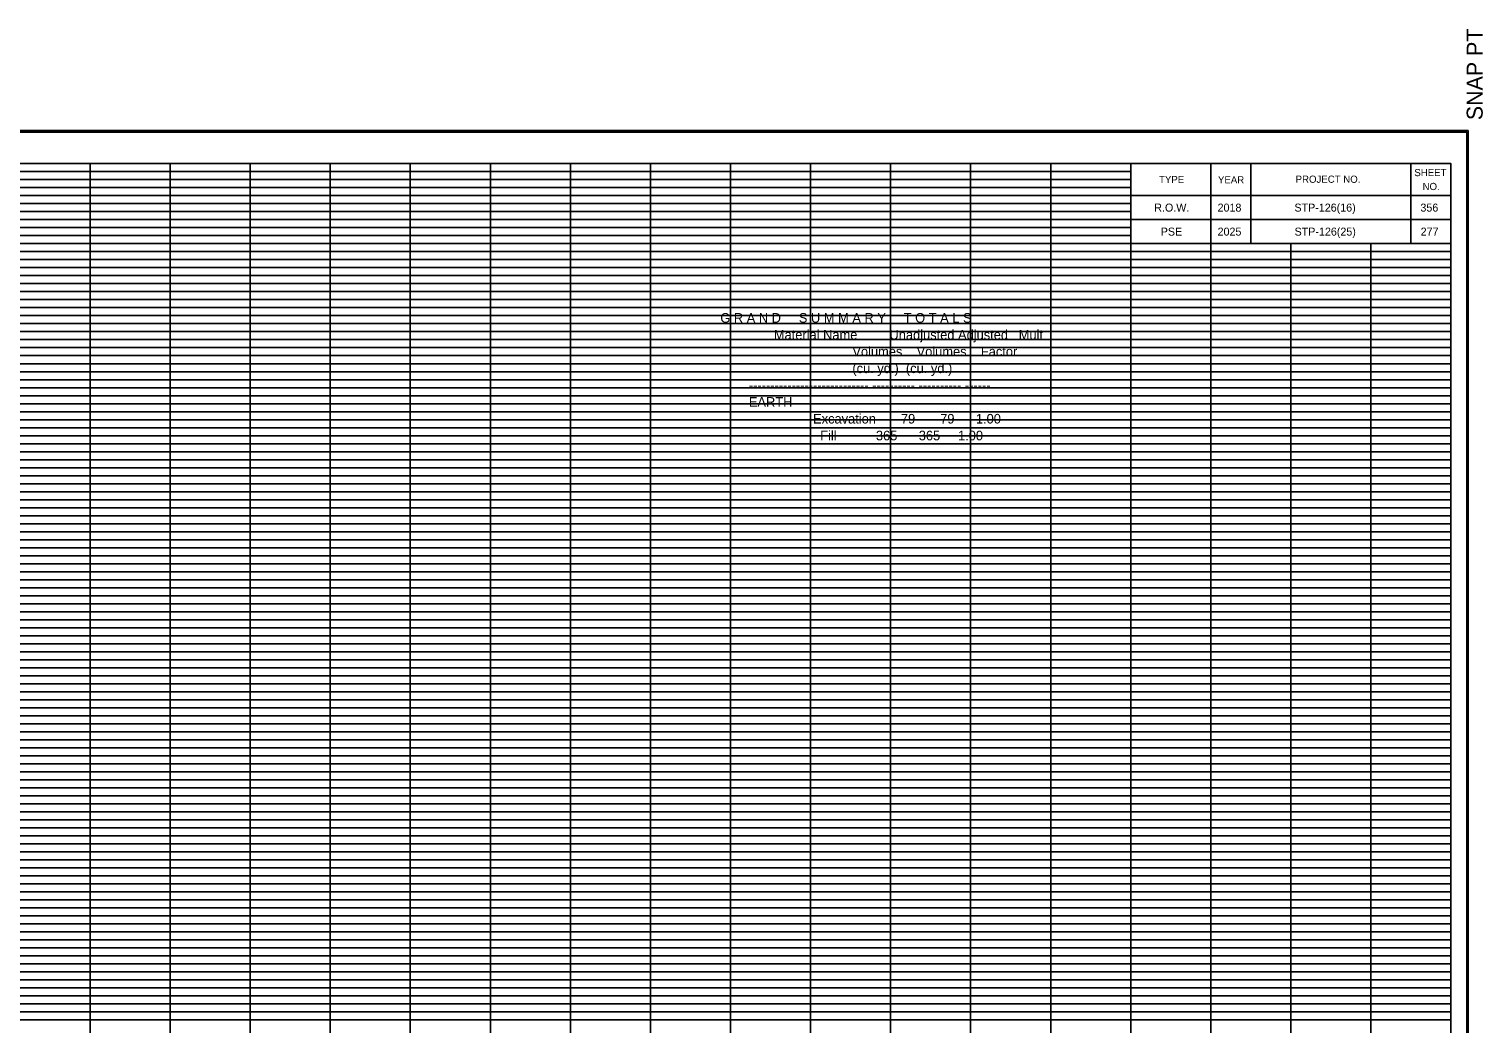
# Model space of a CAD drawing. Extents: x 980 to 1324, y 978 to 1497.
# Drawn here: x 1142.4 to 1324, y 1372.5 to 1496.8 of the extents above; entities that cross this region are included whole.
import ezdxf

# ---------------------------------------------------------------- set-up
doc = ezdxf.new("R2010")
doc.units = 0
for name, color, linetype in [('DESIGN - SCRATCH - User 1', 7, 'Continuous'), ('DESIGN - SHEET - Corner Text', 7, 'Continuous'), ('DESIGN - SHEET - Light Grid', 7, 'Continuous'), ('DESIGN - SHEET - Linework', 7, 'Continuous'), ('DESIGN - SHEET - Plot Shape', 7, 'Continuous'), ('DESIGN - TYPICAL - Finished Grade and Subgrade', 7, 'Continuous'), ('DESIGN - TYPICAL - Text', 7, 'Continuous')]:
    doc.layers.add(name, color=color, linetype=linetype)

# ---------------------------------------------------------------- blocks, each defined once
blk = doc.blocks.new('XSTSHT')
at = {"layer": 'DESIGN - SCRATCH - User 1'}
for p, q in [((28.5, 20.45), (28.5, 20.45)), ((29.24, 20.45), (29.24, 20.45)), ((30.49, 20.45), (30.49, 20.45)), ((31.74, 20.45), (31.74, 20.45)), ((28.5, 20.15), (28.5, 20.15)), ((29.24, 20.15), (29.24, 20.15)), ((30.49, 20.15), (30.49, 20.15)), ((31.74, 20.15), (31.74, 20.15))]:
    blk.add_line(p, q, dxfattribs=at)
at = {"layer": 'DESIGN - SHEET - Light Grid'}
for p, q in [((8, 20.9), (16, 20.9)), ((16, 20.9), (24, 20.9)), ((24, 20.9), (28, 20.9)), ((8, 20.8), (16, 20.8)), ((16, 20.8), (24, 20.8)), ((24, 20.8), (28, 20.8)), ((8, 20.7), (16, 20.7)), ((8, 20.6), (16, 20.6)), ((16, 20.7), (24, 20.7)), ((16, 20.6), (24, 20.6)), ((24, 20.7), (28, 20.7)), ((24, 20.6), (28, 20.6)), ((8, 20.5), (16, 20.5)), ((8, 20.4), (16, 20.4)), ((16, 20.5), (24, 20.5)), ((16, 20.4), (24, 20.4)), ((24, 20.5), (28, 20.5)), ((24, 20.4), (28, 20.4)), ((8, 20.3), (16, 20.3)), ((8, 20.2), (16, 20.2)), ((16, 20.3), (24, 20.3)), ((16, 20.2), (24, 20.2)), ((24, 20.3), (28, 20.3)), ((24, 20.2), (28, 20.2)), ((8, 20.1), (16, 20.1)), ((16, 20.1), (24, 20.1)), ((24, 20.1), (28, 20.1)), ((8, 19.9), (16, 19.9)), ((8, 19.8), (16, 19.8)), ((16, 19.9), (24, 19.9)), ((16, 19.8), (24, 19.8)), ((24, 19.9), (32, 19.9)), ((24, 19.8), (32, 19.8)), ((8, 19.7), (16, 19.7)), ((16, 19.7), (24, 19.7)), ((24, 19.7), (32, 19.7)), ((8, 19.6), (16, 19.6)), ((8, 19.5), (16, 19.5)), ((16, 19.6), (24, 19.6)), ((16, 19.5), (24, 19.5)), ((24, 19.6), (32, 19.6)), ((24, 19.5), (32, 19.5)), ((8, 19.4), (16, 19.4)), ((8, 19.3), (16, 19.3)), ((16, 19.4), (24, 19.4)), ((16, 19.3), (24, 19.3)), ((24, 19.4), (32, 19.4)), ((24, 19.3), (32, 19.3)), ((8, 19.2), (16, 19.2)), ((8, 19.1), (16, 19.1)), ((16, 19.2), (24, 19.2)), ((16, 19.1), (24, 19.1)), ((24, 19.2), (32, 19.2)), ((24, 19.1), (32, 19.1)), ((8, 18.9), (16, 18.9)), ((16, 18.9), (24, 18.9)), ((24, 18.9), (32, 18.9)), ((8, 18.8), (16, 18.8)), ((16, 18.8), (24, 18.8)), ((24, 18.8), (32, 18.8)), ((8, 18.7), (16, 18.7)), ((8, 18.6), (16, 18.6)), ((16, 18.7), (24, 18.7)), ((16, 18.6), (24, 18.6)), ((24, 18.7), (32, 18.7)), ((24, 18.6), (32, 18.6)), ((8, 18.5), (16, 18.5)), ((8, 18.4), (16, 18.4)), ((16, 18.5), (24, 18.5)), ((16, 18.4), (24, 18.4)), ((24, 18.5), (32, 18.5)), ((24, 18.4), (32, 18.4)), ((8, 18.3), (16, 18.3)), ((8, 18.2), (16, 18.2)), ((16, 18.3), (24, 18.3)), ((16, 18.2), (24, 18.2)), ((24, 18.3), (32, 18.3)), ((24, 18.2), (32, 18.2)), ((8, 18.1), (16, 18.1)), ((16, 18.1), (24, 18.1)), ((24, 18.1), (32, 18.1)), ((8, 17.9), (16, 17.9)), ((8, 17.8), (16, 17.8)), ((16, 17.9), (24, 17.9)), ((16, 17.8), (24, 17.8)), ((24, 17.9), (32, 17.9)), ((24, 17.8), (32, 17.8)), ((8, 17.7), (16, 17.7)), ((16, 17.7), (24, 17.7)), ((24, 17.7), (32, 17.7)), ((8, 17.6), (16, 17.6)), ((8, 17.5), (16, 17.5)), ((16, 17.6), (24, 17.6)), ((16, 17.5), (24, 17.5)), ((24, 17.6), (32, 17.6)), ((24, 17.5), (32, 17.5)), ((8, 17.4), (16, 17.4)), ((8, 17.3), (16, 17.3)), ((16, 17.4), (24, 17.4)), ((16, 17.3), (24, 17.3)), ((24, 17.4), (32, 17.4)), ((24, 17.3), (32, 17.3)), ((8, 17.2), (16, 17.2)), ((8, 17.1), (16, 17.1)), ((16, 17.2), (24, 17.2)), ((16, 17.1), (24, 17.1)), ((24, 17.2), (32, 17.2)), ((24, 17.1), (32, 17.1)), ((8, 16.9), (16, 16.9)), ((16, 16.9), (24, 16.9)), ((24, 16.9), (32, 16.9)), ((8, 16.8), (16, 16.8)), ((16, 16.8), (24, 16.8)), ((24, 16.8), (32, 16.8)), ((8, 16.7), (16, 16.7)), ((8, 16.6), (16, 16.6)), ((16, 16.7), (24, 16.7)), ((16, 16.6), (24, 16.6)), ((24, 16.7), (32, 16.7)), ((24, 16.6), (32, 16.6)), ((8, 16.5), (16, 16.5)), ((8, 16.4), (16, 16.4)), ((16, 16.5), (24, 16.5)), ((16, 16.4), (24, 16.4)), ((24, 16.5), (32, 16.5)), ((24, 16.4), (32, 16.4)), ((8, 16.3), (16, 16.3)), ((8, 16.2), (16, 16.2)), ((16, 16.3), (24, 16.3)), ((16, 16.2), (24, 16.2)), ((24, 16.3), (32, 16.3)), ((24, 16.2), (32, 16.2)), ((8, 16.1), (16, 16.1)), ((16, 16.1), (24, 16.1)), ((24, 16.1), (32, 16.1)), ((8, 15.9), (16, 15.9)), ((16, 15.9), (24, 15.9)), ((24, 15.9), (32, 15.9)), ((8, 15.8), (16, 15.8)), ((8, 15.7), (16, 15.7)), ((16, 15.8), (24, 15.8)), ((16, 15.7), (24, 15.7)), ((24, 15.8), (32, 15.8)), ((24, 15.7), (32, 15.7)), ((8, 15.6), (16, 15.6)), ((8, 15.5), (16, 15.5)), ((16, 15.6), (24, 15.6)), ((16, 15.5), (24, 15.5)), ((24, 15.6), (32, 15.6)), ((24, 15.5), (32, 15.5)), ((8, 15.4), (16, 15.4)), ((8, 15.3), (16, 15.3)), ((16, 15.4), (24, 15.4)), ((16, 15.3), (24, 15.3)), ((24, 15.4), (32, 15.4)), ((24, 15.3), (32, 15.3)), ((8, 15.2), (16, 15.2)), ((8, 15.1), (16, 15.1)), ((16, 15.2), (24, 15.2)), ((16, 15.1), (24, 15.1)), ((24, 15.2), (32, 15.2)), ((24, 15.1), (32, 15.1)), ((8, 14.9), (16, 14.9)), ((16, 14.9), (24, 14.9)), ((24, 14.9), (32, 14.9)), ((8, 14.8), (16, 14.8)), ((16, 14.8), (24, 14.8)), ((24, 14.8), (32, 14.8)), ((8, 14.7), (16, 14.7)), ((8, 14.6), (16, 14.6)), ((16, 14.7), (24, 14.7)), ((16, 14.6), (24, 14.6)), ((24, 14.7), (32, 14.7)), ((24, 14.6), (32, 14.6)), ((8, 14.5), (16, 14.5)), ((8, 14.4), (16, 14.4)), ((16, 14.5), (24, 14.5)), ((16, 14.4), (24, 14.4)), ((24, 14.5), (32, 14.5)), ((24, 14.4), (32, 14.4)), ((8, 14.3), (16, 14.3)), ((8, 14.2), (16, 14.2)), ((16, 14.3), (24, 14.3)), ((16, 14.2), (24, 14.2)), ((24, 14.3), (32, 14.3)), ((24, 14.2), (32, 14.2)), ((8, 14.1), (16, 14.1)), ((16, 14.1), (24, 14.1)), ((24, 14.1), (32, 14.1)), ((8, 13.9), (16, 13.9)), ((16, 13.9), (24, 13.9)), ((24, 13.9), (32, 13.9)), ((8, 13.8), (16, 13.8)), ((8, 13.7), (16, 13.7)), ((16, 13.8), (24, 13.8)), ((16, 13.7), (24, 13.7)), ((24, 13.8), (32, 13.8)), ((24, 13.7), (32, 13.7)), ((8, 13.6), (16, 13.6)), ((8, 13.5), (16, 13.5)), ((16, 13.6), (24, 13.6)), ((16, 13.5), (24, 13.5)), ((24, 13.6), (32, 13.6)), ((24, 13.5), (32, 13.5)), ((8, 13.4), (16, 13.4)), ((8, 13.3), (16, 13.3)), ((16, 13.4), (24, 13.4)), ((16, 13.3), (24, 13.3)), ((24, 13.4), (32, 13.4)), ((24, 13.3), (32, 13.3)), ((8, 13.2), (16, 13.2)), ((8, 13.1), (16, 13.1)), ((16, 13.2), (24, 13.2)), ((16, 13.1), (24, 13.1)), ((24, 13.2), (32, 13.2)), ((24, 13.1), (32, 13.1)), ((8, 12.9), (16, 12.9)), ((16, 12.9), (24, 12.9)), ((24, 12.9), (32, 12.9)), ((8, 12.8), (16, 12.8)), ((16, 12.8), (24, 12.8)), ((24, 12.8), (32, 12.8)), ((8, 12.7), (16, 12.7)), ((8, 12.6), (16, 12.6)), ((16, 12.7), (24, 12.7)), ((16, 12.6), (24, 12.6)), ((24, 12.7), (32, 12.7)), ((24, 12.6), (32, 12.6)), ((8, 12.5), (16, 12.5)), ((8, 12.4), (16, 12.4)), ((16, 12.5), (24, 12.5)), ((16, 12.4), (24, 12.4)), ((24, 12.5), (32, 12.5)), ((24, 12.4), (32, 12.4)), ((8, 12.3), (16, 12.3)), ((8, 12.2), (16, 12.2)), ((16, 12.3), (24, 12.3)), ((16, 12.2), (24, 12.2)), ((24, 12.3), (32, 12.3)), ((24, 12.2), (32, 12.2)), ((8, 12.1), (16, 12.1)), ((16, 12.1), (24, 12.1)), ((24, 12.1), (32, 12.1)), ((8, 11.9), (16, 11.9)), ((16, 11.9), (24, 11.9)), ((24, 11.9), (32, 11.9)), ((8, 11.8), (16, 11.8)), ((8, 11.7), (16, 11.7)), ((16, 11.8), (24, 11.8)), ((16, 11.7), (24, 11.7)), ((24, 11.8), (32, 11.8)), ((24, 11.7), (32, 11.7)), ((8, 11.6), (16, 11.6)), ((8, 11.5), (16, 11.5)), ((16, 11.6), (24, 11.6)), ((16, 11.5), (24, 11.5)), ((24, 11.6), (32, 11.6)), ((24, 11.5), (32, 11.5)), ((8, 11.4), (16, 11.4)), ((8, 11.3), (16, 11.3)), ((16, 11.4), (24, 11.4)), ((16, 11.3), (24, 11.3)), ((24, 11.4), (32, 11.4)), ((24, 11.3), (32, 11.3)), ((8, 11.2), (16, 11.2)), ((8, 11.1), (16, 11.1)), ((16, 11.2), (24, 11.2)), ((16, 11.1), (24, 11.1)), ((24, 11.2), (32, 11.2)), ((24, 11.1), (32, 11.1)), ((8, 10.9), (16, 10.9)), ((16, 10.9), (24, 10.9)), ((24, 10.9), (32, 10.9)), ((8, 10.8), (16, 10.8)), ((16, 10.8), (24, 10.8)), ((24, 10.8), (32, 10.8)), ((8, 10.7), (16, 10.7)), ((8, 10.6), (16, 10.6)), ((16, 10.7), (24, 10.7)), ((16, 10.6), (24, 10.6)), ((24, 10.7), (32, 10.7)), ((24, 10.6), (32, 10.6)), ((8, 10.5), (16, 10.5)), ((8, 10.4), (16, 10.4)), ((16, 10.5), (24, 10.5)), ((16, 10.4), (24, 10.4)), ((24, 10.5), (32, 10.5)), ((24, 10.4), (32, 10.4)), ((8, 10.3), (16, 10.3)), ((16, 10.3), (24, 10.3)), ((24, 10.3), (32, 10.3))]:
    blk.add_line(p, q, dxfattribs=at)
at = {"layer": 'DESIGN - SHEET - Linework'}
for p, q in [((-1.823, 21.414), (32.217, 21.414)), ((32.217, 21.414), (32.217, -0.414)), ((15, 0), (15, 21)), ((16, 0), (16, 21)), ((17, 0), (17, 21)), ((18, 0), (18, 21)), ((19, 0), (19, 21)), ((20, 0), (20, 21)), ((21, 0), (21, 21)), ((22, 0), (22, 21)), ((23, 0), (23, 21)), ((24, 0), (24, 21)), ((25, 0), (25, 21)), ((26, 0), (26, 21)), ((27, 0), (27, 21)), ((0, 20), (28, 20)), ((28, 0), (28, 20)), ((29, 0), (29, 20)), ((30, 0), (30, 20)), ((31, 0), (31, 20)), ((0, 19), (32, 19)), ((0, 18), (32, 18)), ((0, 17), (32, 17)), ((0, 16), (32, 16)), ((0, 15), (32, 15)), ((0, 14), (32, 14)), ((0, 13), (32, 13)), ((0, 12), (32, 12)), ((0, 11), (32, 11))]:
    blk.add_line(p, q, dxfattribs=at)
for points in [[(0, 21), (0, 0), (32, 0), (32, 21), (0, 21)], [(28, 21), (28, 20), (32, 20), (32, 21), (31.5, 21), (31.5, 20), (29.5, 20), (29.5, 21), (29, 21), (29, 20), (32, 20), (28, 20), (28, 20.3), (32, 20.3), (32, 20.6), (28, 20.6)]]:
    blk.add_lwpolyline(points, dxfattribs=at)
at = {"layer": 'DESIGN - SHEET - Plot Shape'}
for points in [[(-1.803, 21.394), (32.197, 21.394), (32.197, -0.394), (-1.803, -0.394)], [(-0.85, 21), (32, 21), (32, -0.25), (-0.85, -0.25)]]:
    blk.add_lwpolyline(points, close=True, dxfattribs=at)
at = {"layer": 'DESIGN - SHEET - Corner Text'}
blk.add_text('  SNAP PT', height=0.2, rotation=90, dxfattribs=at).set_placement((32.397, 21.394))
for s, p in [('SHEET', (31.543, 20.843)), ('TYPE', (28.354, 20.756)), ('YEAR', (29.09, 20.752)), ('PROJECT NO.', (30.06, 20.76)), ('NO.', (31.646, 20.669))]:
    blk.add_text(s, height=0.09, dxfattribs=at).set_placement(p)

msp = doc.modelspace()

# ---------------------------------------------------------------- linework, layer by layer
at = {"layer": 'DESIGN - SHEET - Plot Shape'}
msp.add_lwpolyline([(991.5, 1267.5), (1320, 1267.5), (1320, 1480), (991.5, 1480)], close=True, dxfattribs=at)

# ---------------------------------------------------------------- block references
at = {"layer": 'DESIGN - TYPICAL - Finished Grade and Subgrade', "xscale": 10, "yscale": 10}
msp.add_blockref('XSTSHT', (1000, 1270), dxfattribs=at)

# ---------------------------------------------------------------- texts
at = {"layer": 'DESIGN - SHEET - Corner Text'}
for s, p in [('R.O.W.', (1282.94, 1474)), ('2018', (1290.85, 1474)), ('STP-126(16)', (1300.45, 1474)), ('356', (1316.19, 1474)), ('PSE', (1283.75, 1471)), ('2025', (1290.85, 1471)), ('STP-126(25)', (1300.47, 1471)), ('277', (1316.22, 1471))]:
    msp.add_text(s, height=1, dxfattribs=at).set_placement(p)
at = {"layer": 'DESIGN - TYPICAL - Text'}
for s, p in [('G R A N D     S U M M A R Y     T O T A L S', (1228.73, 1460.12)), ('               Material Name         Unadjusted Adjusted   Mult', (1228.73, 1458.02)), ('                                     Volumes    Volumes    Factor', (1228.73, 1455.92)), ('                                     (cu. yd.)  (cu. yd.)', (1228.73, 1453.82)), ('        ---------------------------- ---------- ---------- ------', (1228.73, 1451.72)), ('        EARTH', (1228.73, 1449.62)), ('                          Excavation       79       79      1.00', (1228.73, 1447.52)), ('                            Fill           365      365     1.00', (1228.73, 1445.42))]:
    msp.add_text(s, height=1.2, dxfattribs=at).set_placement(p)

doc.saveas('drawing.dxf')
